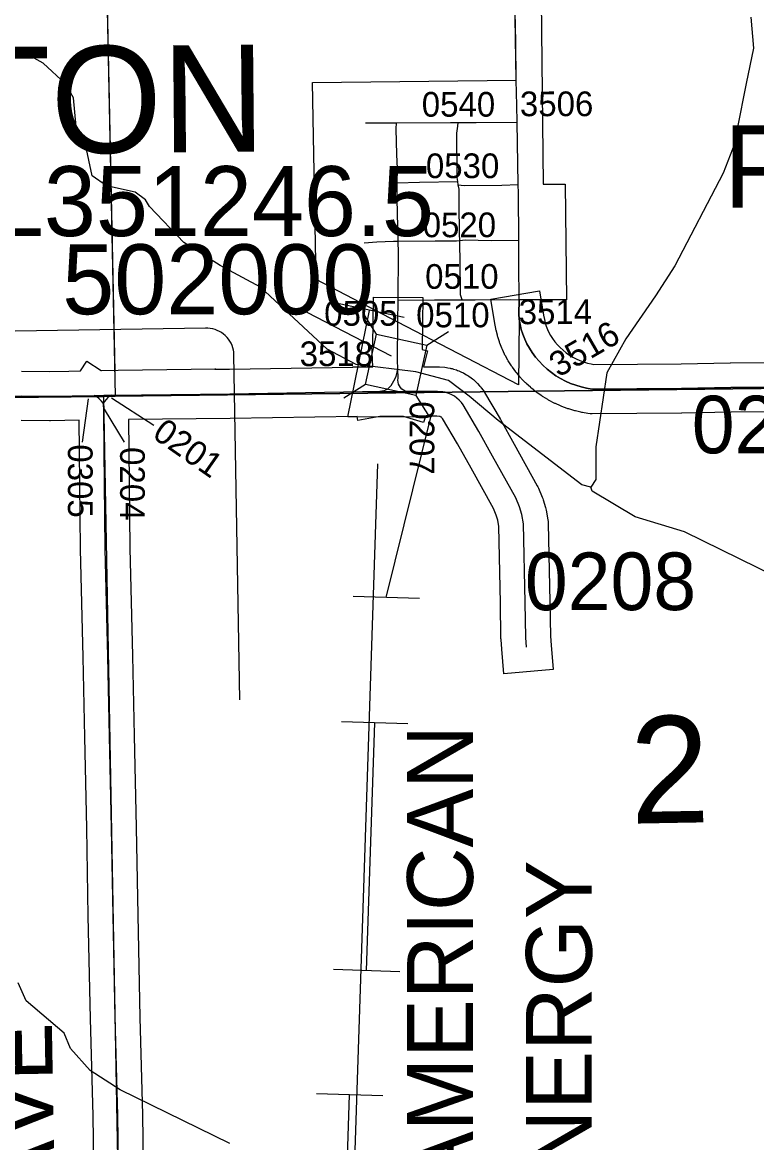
# Model space of a CAD drawing. Extents: x 23.6 to 68.7, y -63 to -29.
# Drawn here: x 36.588 to 37.481, y -46.611 to -45.249 of the extents above; entities that cross this region are included whole.
import ezdxf

# ---------------------------------------------------------------- set-up
doc = ezdxf.new("R2010")
doc.units = 0
for name, color, linetype in [('tdCoCityStreetMinor', 7, 'Continuous'), ('tdCoCorpBndry', 7, 'Continuous'), ('tdCoCorpPopTxt', 7, 'Continuous'), ('tdCoCorpTxt', 7, 'Continuous'), ('tdCoDirctArrow', 7, 'Continuous'), ('tdCoHydroRiver', 7, 'Continuous'), ('tdCoPipe', 7, 'Continuous'), ('tdCoPipeTxt', 7, 'Continuous'), ('tdCoSecRdNmbr', 7, 'Continuous'), ('tdCoSecRdTxt', 7, 'Continuous'), ('tdCoSecRteBand', 7, 'Continuous'), ('tdCoSecRteCL', 7, 'Continuous'), ('tdCoSectLine', 7, 'Continuous'), ('tdCoSectLinePart', 7, 'Continuous'), ('tdCoSectNmbr', 7, 'Continuous'), ('tdCoStrucSec', 7, 'Continuous'), ('tdCoStrucSecCoName', 7, 'Continuous'), ('tdCoStrucSecFHWANum', 7, 'Continuous'), ('tdCoSurfAsphalt', 7, 'Continuous'), ('tdCoSurfAsphaltUnbanded', 7, 'Continuous'), ('tdCoSurfConcUnbanded', 7, 'Continuous'), ('tdCoSurfGravel', 7, 'Continuous'), ('tdCoTwpBndryShd', 7, 'Continuous')]:
    doc.layers.add(name, color=color, linetype=linetype)

msp = doc.modelspace()

# ---------------------------------------------------------------- linework, layer by layer
at = {"layer": 'tdCoCityStreetMinor'}
for p, q in [((37.0054, -45.3713), (37.0429, -45.3713)), ((37.1181, -45.4467), (37.1175, -45.4426))]:
    msp.add_line(p, q, dxfattribs=at)
for points in [[(37.0439, -45.4442), (37.044, -45.4269), (37.0435, -45.41), (37.0424, -45.3787), (37.0429, -45.3713)], [(37.0429, -45.3713), (37.1088, -45.3711), (37.1181, -45.3711)], [(37.1175, -45.4426), (37.1168, -45.4379), (37.1163, -45.384), (37.1175, -45.3755), (37.1181, -45.3711)], [(37.1181, -45.3711), (37.14, -45.3709), (37.1895, -45.3707)], [(37.0451, -45.5153), (37.0437, -45.4637), (37.0439, -45.4442)], [(37.0439, -45.4442), (37.0711, -45.4435), (37.1175, -45.4426)], [(37.1181, -45.4467), (37.1254, -45.4476), (37.1711, -45.4473), (37.1909, -45.4463)], [(37.1198, -45.5143), (37.1196, -45.5067), (37.1193, -45.4698), (37.119, -45.4522), (37.1181, -45.4467)], [(37.0037, -45.5175), (37.0192, -45.516), (37.0392, -45.5154), (37.0451, -45.5153)], [(37.0449, -45.5869), (37.0455, -45.5293), (37.0451, -45.5153)], [(37.0451, -45.5153), (37.0899, -45.5149), (37.1159, -45.5147), (37.1198, -45.5143)], [(37.1198, -45.5143), (37.1264, -45.5136), (37.1579, -45.5144), (37.1915, -45.5139)], [(37.1226, -45.5866), (37.1209, -45.5806), (37.1208, -45.5737), (37.1198, -45.5143)]]:
    msp.add_lwpolyline(points, dxfattribs=at)
at = {"layer": 'tdCoCorpBndry'}
msp.add_lwpolyline([(37.2974, -45.1915), (37.2983, -45.2218), (37.2187, -45.2226), (37.2214, -45.446), (37.2481, -45.4462), (37.2495, -45.5866), (37.1921, -45.5865), (37.1916, -45.6041), (37.1922, -45.6103), (37.1912, -45.6899), (37.0447, -45.6136), (36.9452, -45.5618), (36.9409, -45.3224), (37.1886, -45.3197), (37.1866, -45.1925)], close=True, dxfattribs=at)
at = {"layer": 'tdCoDirctArrow'}
msp.add_lwpolyline([(36.8525, -46.0728), (36.8454, -45.6535), (36.8451, -45.6499), (36.8447, -45.6477), (36.844, -45.6448), (36.8431, -45.6421), (36.8419, -45.6394), (36.8404, -45.6369), (36.8388, -45.6345), (36.837, -45.6322), (36.8349, -45.6301), (36.8327, -45.6282), (36.8303, -45.6265), (36.8278, -45.625), (36.8252, -45.6238), (36.8224, -45.6228), (36.8196, -45.622), (36.8167, -45.6215), (36.8138, -45.6212), (36.8109, -45.6212), (36.4251, -45.6272)], dxfattribs=at)
at = {"layer": 'tdCoHydroRiver'}
for points in [[(37.4735, -45.243), (37.4769, -45.2808), (37.4678, -45.3235), (37.4572, -45.3789), (37.4542, -45.3963), (37.4402, -45.4327), (37.3812, -45.5452), (37.3578, -45.5817), (37.3219, -45.6341), (37.2985, -45.6753), (37.2851, -45.7654), (37.2854, -45.8049), (37.2791, -45.8144)], [(37.2791, -45.8144), (37.2681, -45.8113), (37.1664, -45.7332), (37.1315, -45.7035), (37.106, -45.6848), (37.0665, -45.674), (36.9938, -45.6652), (36.9589, -45.6465), (36.8778, -45.5714), (36.8287, -45.5449), (36.7843, -45.5169), (36.7429, -45.473), (36.7381, -45.4652), (36.7254, -45.4558), (36.6906, -45.4482), (36.6731, -45.4357), (36.6649, -45.3979), (36.6537, -45.3759), (36.6503, -45.3412), (36.6407, -45.3239), (36.6136, -45.2988), (36.5772, -45.2786)], [(38.2852, -46.2735), (38.2443, -46.2896), (38.2111, -46.2883), (37.8069, -46.0785), (37.7199, -46.0508), (37.6564, -46.0118), (37.6262, -45.9868), (37.5929, -45.9666), (37.3932, -45.8687), (37.3331, -45.8503), (37.2808, -45.8191), (37.2791, -45.8144)], [(36.8404, -46.6119), (36.7073, -46.5467), (36.6708, -46.5233), (36.6469, -46.4967), (36.6389, -46.4778), (36.5928, -46.4387), (36.5831, -46.4167)]]:
    msp.add_lwpolyline(points, dxfattribs=at)
at = {"layer": 'tdCoPipe'}
for p, q in [((37.0523, -45.6082), (36.9735, -45.5916)), ((37.0708, -45.9497), (36.9903, -45.9471)), ((37.0568, -46.102), (36.9761, -46.0994)), ((37.0469, -46.4032), (36.9664, -46.4005)), ((37.0262, -46.5542), (36.9456, -46.5516))]:
    msp.add_line(p, q, dxfattribs=at)
for points in [[(37.0305, -45.9484), (37.0848, -45.7291), (36.9839, -45.7287), (37.0102, -45.5995)], [(36.6897, -48.1748), (36.9749, -47.1608), (37.0201, -45.7858)], [(37.0066, -46.4018), (37.0165, -46.1007)], [(36.976, -46.854), (36.9859, -46.5529)]]:
    msp.add_lwpolyline(points, dxfattribs=at)
at = {"layer": 'tdCoSecRdNmbr'}
for p, q in [((36.7479, -45.7394), (36.6966, -45.7061)), ((36.7125, -45.7598), (36.6879, -45.7196))]:
    msp.add_line(p, q, dxfattribs=at)
msp.add_lwpolyline([(36.6612, -45.7594), (36.6688, -45.707), (36.6688, -45.707)], dxfattribs=at)
at = {"layer": 'tdCoSecRteBand'}
for points in [[(36.5871, -45.6732), (36.6216, -45.6737), (36.6449, -45.6732), (36.6449, -45.6731), (36.659, -45.6729), (36.6666, -45.6611), (36.684, -45.6725), (36.6843, -45.6725), (36.7048, -45.6721), (36.7048, -45.6722), (36.823, -45.6705), (36.8223, -45.6709), (36.84, -45.6707), (36.99, -45.6684), (36.99, -45.6682), (37.0012, -45.6682), (37.0015, -45.6682), (37.0143, -45.6682), (37.0144, -45.6681), (37.0132, -45.6422), (37.0144, -45.6422), (37.0147, -45.6133), (37.015, -45.5833), (37.075, -45.5839), (37.0747, -45.6139), (37.0743, -45.6469), (37.0805, -45.6484), (37.0759, -45.6681), (37.0927, -45.668), (37.094, -45.668), (37.0953, -45.6681), (37.1017, -45.6686), (37.1036, -45.6687), (37.1055, -45.6691), (37.1082, -45.6697), (37.1091, -45.6699), (37.1107, -45.6702), (37.1122, -45.6707), (37.1158, -45.6718), (37.1173, -45.6723), (37.1187, -45.6729), (37.1221, -45.6744), (37.1236, -45.6751), (37.1249, -45.6758), (37.1282, -45.6777), (37.1296, -45.6785), (37.1308, -45.6794), (37.1339, -45.6816), (37.1352, -45.6825), (37.1364, -45.6835), (37.1392, -45.686), (37.1403, -45.6871), (37.1414, -45.6882), (37.1439, -45.691), (37.145, -45.6921), (37.1459, -45.6934), (37.1482, -45.6964), (37.1491, -45.6977), (37.1499, -45.6991), (37.1689, -45.7314), (37.1691, -45.7317), (37.1692, -45.732), (37.186, -45.7621), (37.186, -45.7621), (37.186, -45.7621), (37.2141, -45.8126), (37.2149, -45.814), (37.2155, -45.8155), (37.2202, -45.8266), (37.2209, -45.8282), (37.2213, -45.8298), (37.2241, -45.8389), (37.2246, -45.8406), (37.2249, -45.8424), (37.2269, -45.854), (37.2272, -45.8562), (37.2273, -45.8584), (37.2292, -45.9538), (37.2292, -45.9539), (37.2292, -45.9539), (37.23, -45.9954), (37.2309, -46.0062), (37.2334, -46.0361), (37.1736, -46.0411), (37.1711, -46.0112), (37.1701, -45.9994), (37.17, -45.9984), (37.17, -45.9974), (37.1693, -45.955), (37.1673, -45.8619), (37.166, -45.8542), (37.1643, -45.8484), (37.1609, -45.8404), (37.1336, -45.7913), (37.117, -45.7615), (37.099, -45.7308), (37.0986, -45.7303), (37.0982, -45.7299), (37.0977, -45.7294), (37.0972, -45.7291), (37.0966, -45.7288), (37.0961, -45.7285), (37.0954, -45.7283), (37.0952, -45.7282), (37.0919, -45.728), (37.0859, -45.7281), (37.0859, -45.7282), (37.0781, -45.7282), (37.0758, -45.7357), (37.0514, -45.7282), (37.05, -45.7282), (37.0401, -45.7282), (37.0259, -45.7282), (37.0228, -45.7282), (36.996, -45.7332), (36.9951, -45.7283), (36.8409, -45.7307), (36.8408, -45.7307), (36.8408, -45.7307), (36.7172, -45.7321), (36.7175, -45.7697), (36.719, -45.8886), (36.722, -46.0194), (36.7243, -46.1166), (36.7243, -46.1166), (36.7243, -46.1167), (36.7266, -46.2277), (36.7266, -46.2277), (36.7266, -46.2278), (36.7284, -46.3345), (36.7312, -46.4587), (36.7341, -46.5772), (36.7341, -46.5774), (36.7341, -46.5775), (36.7358, -46.6934)], [(37.6364, -45.7223), (37.4496, -45.723), (37.39, -45.7243), (37.3898, -45.7243), (37.3895, -45.7243), (37.2807, -45.725), (37.2782, -45.725), (37.2757, -45.7246), (37.269, -45.7235), (37.2681, -45.7234), (37.2671, -45.7231), (37.2606, -45.7216), (37.2597, -45.7214), (37.2587, -45.7211), (37.2523, -45.7192), (37.2514, -45.7189), (37.2504, -45.7186), (37.2441, -45.7163), (37.2432, -45.7159), (37.2424, -45.7155), (37.2362, -45.7128), (37.2353, -45.7124), (37.2345, -45.712), (37.2285, -45.7088), (37.2277, -45.7084), (37.2268, -45.7079), (37.2211, -45.7044), (37.2203, -45.7039), (37.2195, -45.7033), (37.214, -45.6995), (37.2132, -45.6989), (37.2124, -45.6983), (37.2072, -45.6941), (37.2064, -45.6935), (37.2057, -45.6928), (37.2007, -45.6883), (37.2, -45.6876), (37.1994, -45.6869), (37.1947, -45.6821), (37.194, -45.6814), (37.1934, -45.6807), (37.1891, -45.6755), (37.1885, -45.6748), (37.1879, -45.674), (37.1839, -45.6686), (37.1833, -45.6678), (37.1828, -45.667), (37.1794, -45.6618), (37.1789, -45.6609), (37.1784, -45.6601), (37.1753, -45.6546), (37.1748, -45.6537), (37.1744, -45.6528), (37.1717, -45.6471), (37.1713, -45.6462), (37.1709, -45.6453), (37.1687, -45.6394), (37.1683, -45.6385), (37.168, -45.6375), (37.1661, -45.6316), (37.1658, -45.6306), (37.1656, -45.6296), (37.1641, -45.6235), (37.1639, -45.6225), (37.1637, -45.6215), (37.1626, -45.6154), (37.1576, -45.5858), (37.2167, -45.5756), (37.2218, -45.6052), (37.2227, -45.6104), (37.2237, -45.6145), (37.2249, -45.6186), (37.2265, -45.6225), (37.2283, -45.6263), (37.2303, -45.6301), (37.2327, -45.6337), (37.2355, -45.6376), (37.2386, -45.6412), (37.242, -45.6447), (37.2455, -45.6479), (37.2492, -45.6509), (37.2532, -45.6537), (37.2573, -45.6562), (37.2615, -45.6584), (37.2659, -45.6603), (37.2704, -45.662), (37.275, -45.6634), (37.2796, -45.6644), (37.2828, -45.665), (37.3889, -45.6643), (37.4485, -45.663), (37.4488, -45.663), (37.4491, -45.663), (37.6361, -45.6624)], [(36.6758, -46.6943), (36.6742, -46.5786), (36.6712, -46.4602), (36.6712, -46.4601), (36.6712, -46.4601), (36.6684, -46.3358), (36.6684, -46.3357), (36.6684, -46.3356), (36.6666, -46.2288), (36.6643, -46.118), (36.662, -46.0209), (36.662, -46.0208), (36.662, -46.0208), (36.659, -45.8898), (36.659, -45.8896), (36.659, -45.8895), (36.6575, -45.7705), (36.6575, -45.7704), (36.6575, -45.7704), (36.6572, -45.733), (36.6223, -45.7337), (36.6218, -45.7337), (36.6213, -45.7337), (36.5866, -45.7332)]]:
    msp.add_lwpolyline(points, dxfattribs=at)
at = {"layer": 'tdCoSecRteCL'}
for points in [[(37.1921, -45.5865), (37.1917, -45.5437), (37.1915, -45.5139), (37.1911, -45.4568), (37.1909, -45.4463), (37.1895, -45.3707), (37.1895, -45.3707), (37.1891, -45.3504), (37.1886, -45.3197), (37.1886, -45.3193), (37.1879, -45.273), (37.1871, -45.2365)], [(37.0445, -45.6709), (37.0442, -45.6597), (37.0447, -45.6136), (37.0449, -45.5869), (37.0892, -45.5867), (37.1226, -45.5866), (37.1386, -45.5865), (37.1819, -45.5863), (37.1921, -45.5865)], [(37.6363, -45.6923), (37.4492, -45.693), (37.3893, -45.6943), (37.2805, -45.695), (37.2739, -45.6939), (37.2673, -45.6924), (37.2609, -45.6905), (37.2546, -45.6881), (37.2484, -45.6854), (37.2425, -45.6823), (37.2367, -45.6788), (37.2312, -45.6749), (37.226, -45.6707), (37.221, -45.6662), (37.2163, -45.6613), (37.212, -45.6562), (37.208, -45.6508), (37.2046, -45.6455), (37.2016, -45.64), (37.1989, -45.6344), (37.1966, -45.6285), (37.1947, -45.6226), (37.1933, -45.6165), (37.1922, -45.6103), (37.1916, -45.6041), (37.1921, -45.5865)], [(37.02, -45.6982), (37.028, -45.6967), (37.0319, -45.695), (37.0364, -45.6906), (37.0397, -45.6852), (37.0425, -45.6796), (37.0445, -45.6709)], [(37.0559, -45.6982), (37.0536, -45.6975), (37.0514, -45.6964), (37.0495, -45.695), (37.0478, -45.6933), (37.0465, -45.6912), (37.0455, -45.689), (37.0449, -45.6867), (37.0448, -45.6843), (37.045, -45.6819), (37.0445, -45.6709)], [(35.9321, -45.7108), (36.0562, -45.7096), (36.1564, -45.7081), (36.3191, -45.7069), (36.4397, -45.7046), (36.5867, -45.7032), (36.6217, -45.7037), (36.6754, -45.7027)], [(36.6754, -45.7027), (36.6871, -45.7025), (36.6971, -45.7023)], [(36.6867, -45.7127), (36.6843, -45.7098), (36.6815, -45.7071), (36.6786, -45.7047), (36.6754, -45.7027)], [(36.6971, -45.7023), (36.6944, -45.7037), (36.692, -45.7055), (36.6899, -45.7076), (36.6881, -45.71), (36.6867, -45.7127)], [(36.6971, -45.7023), (36.8404, -45.7007), (37.0015, -45.6982), (37.02, -45.6982)], [(37.02, -45.6982), (37.0401, -45.6982), (37.0559, -45.6982)], [(37.201, -46.0087), (37.2, -45.9969), (37.1993, -45.9545), (37.1973, -45.859), (37.1953, -45.8474), (37.1926, -45.8383), (37.1879, -45.8272), (37.1598, -45.7767), (37.143, -45.7466), (37.124, -45.7143), (37.1218, -45.7112), (37.1193, -45.7085), (37.1164, -45.706), (37.1134, -45.7038), (37.1101, -45.7019), (37.1067, -45.7004), (37.1031, -45.6992), (37.1021, -45.699), (37.0994, -45.6985), (37.093, -45.698), (37.0644, -45.6982), (37.0559, -45.6982)], [(36.7129, -47.1747), (36.7124, -47.1509), (36.7106, -47.0309), (36.7096, -46.9323), (36.7078, -46.8099), (36.7058, -46.6939), (36.7041, -46.578), (36.7012, -46.4594), (36.6984, -46.3351), (36.6966, -46.2283), (36.6943, -46.1173), (36.692, -46.0201), (36.689, -45.8891), (36.6875, -45.7701), (36.6871, -45.7211), (36.6867, -45.7127)]]:
    msp.add_lwpolyline(points, dxfattribs=at)
at = {"layer": 'tdCoSectLine'}
for points in [[(36.6803, -44.7056), (36.7012, -45.7036)], [(36.7012, -45.7036), (37.6909, -45.6918)], [(35.6948, -45.7141), (36.6871, -45.7039)], [(36.6871, -45.7039), (36.7012, -45.7036)], [(36.7052, -46.6743), (36.6871, -45.7039)]]:
    msp.add_lwpolyline(points, dxfattribs=at)
at = {"layer": 'tdCoSectLinePart'}
for points in [[(36.6803, -44.7056), (36.7006, -45.6736)], [(37.1489, -45.6982), (37.2118, -45.6975)]]:
    msp.add_lwpolyline(points, dxfattribs=at)
at = {"layer": 'tdCoStrucSec'}
for p, q in [((37.0188, -45.6283), (37.002, -45.6019)), ((37.0799, -45.6418), (37.1063, -45.625)), ((37.0052, -45.6894), (36.9788, -45.7062)), ((37.0663, -45.7029), (37.0831, -45.7293))]:
    msp.add_line(p, q, dxfattribs=at)
msp.add_lwpolyline([(37.0052, -45.6894), (37.0188, -45.6283), (37.0799, -45.6418), (37.0663, -45.7029)], close=True, dxfattribs=at)
at = {"layer": 'tdCoStrucSecFHWANum'}
msp.add_line((36.9342, -45.6017), (37.0365, -45.6545), dxfattribs=at)
at = {"layer": 'tdCoSurfAsphalt'}
msp.add_lwpolyline([(37.1922, -45.6103), (37.1933, -45.6165), (37.1947, -45.6226), (37.1966, -45.6285), (37.1989, -45.6344), (37.2016, -45.64), (37.2046, -45.6455), (37.208, -45.6508), (37.212, -45.6562), (37.2163, -45.6613), (37.221, -45.6662), (37.226, -45.6707), (37.2312, -45.6749), (37.2367, -45.6788), (37.2425, -45.6823), (37.2484, -45.6854), (37.2546, -45.6881), (37.2609, -45.6905), (37.2673, -45.6924), (37.2739, -45.6939), (37.2805, -45.695), (37.3893, -45.6943), (37.4492, -45.693), (37.6363, -45.6923)], dxfattribs=at)
at = {"layer": 'tdCoSurfAsphaltUnbanded'}
msp.add_line((37.0447, -45.6136), (37.0449, -45.5869), dxfattribs=at)
for points in [[(37.1886, -45.3193), (37.1879, -45.273), (37.1871, -45.2365), (37.1866, -45.1925)], [(37.1922, -45.6103), (37.1916, -45.6041), (37.1921, -45.5865)]]:
    msp.add_lwpolyline(points, dxfattribs=at)
at = {"layer": 'tdCoSurfConcUnbanded'}
msp.add_lwpolyline([(37.0449, -45.5869), (37.0892, -45.5867), (37.1226, -45.5866), (37.1386, -45.5865), (37.1819, -45.5863), (37.1921, -45.5865), (37.1917, -45.5437), (37.1915, -45.5139), (37.1911, -45.4568), (37.1909, -45.4463), (37.1895, -45.3707), (37.1895, -45.3707), (37.1891, -45.3504), (37.1886, -45.3197)], dxfattribs=at)
at = {"layer": 'tdCoSurfGravel'}
msp.add_line((37.02, -45.6982), (37.0401, -45.6982), dxfattribs=at)
for points in [[(37.02, -45.6982), (37.028, -45.6967), (37.0319, -45.695), (37.0364, -45.6906), (37.0397, -45.6852), (37.0425, -45.6796), (37.0445, -45.6709), (37.0442, -45.6597), (37.0447, -45.6136)], [(37.0559, -45.6982), (37.0536, -45.6975), (37.0514, -45.6964), (37.0495, -45.695), (37.0478, -45.6933), (37.0465, -45.6912), (37.0455, -45.689), (37.0449, -45.6867), (37.0448, -45.6843), (37.045, -45.6819), (37.0445, -45.6709)], [(36.5867, -45.7032), (36.6217, -45.7037), (36.6754, -45.7027), (36.6871, -45.7025)], [(36.6867, -45.7127), (36.6843, -45.7098), (36.6815, -45.7071), (36.6786, -45.7047), (36.6754, -45.7027)], [(36.6971, -45.7023), (36.6944, -45.7037), (36.692, -45.7055), (36.6899, -45.7076), (36.6881, -45.71), (36.6867, -45.7127)], [(36.6871, -45.7025), (36.6971, -45.7023), (36.8404, -45.7007), (37.0015, -45.6982), (37.02, -45.6982)], [(37.0401, -45.6982), (37.0559, -45.6982), (37.0644, -45.6982), (37.093, -45.698), (37.0994, -45.6985), (37.1021, -45.699)], [(37.201, -46.0087), (37.2, -45.9969), (37.1993, -45.9545), (37.1973, -45.859), (37.1953, -45.8474), (37.1926, -45.8383), (37.1879, -45.8272), (37.1598, -45.7767), (37.143, -45.7466), (37.124, -45.7143), (37.1218, -45.7112), (37.1193, -45.7085), (37.1164, -45.706), (37.1134, -45.7038), (37.1101, -45.7019), (37.1067, -45.7004), (37.1031, -45.6992), (37.1021, -45.699)], [(36.7058, -46.6939), (36.7041, -46.578), (36.7012, -46.4594), (36.6984, -46.3351), (36.6966, -46.2283), (36.6943, -46.1173), (36.692, -46.0201), (36.689, -45.8891), (36.6875, -45.7701), (36.6871, -45.7211), (36.6867, -45.7127)]]:
    msp.add_lwpolyline(points, dxfattribs=at)
at = {"layer": 'tdCoTwpBndryShd'}
msp.add_lwpolyline([(44.659, -45.6063), (43.6569, -45.6219), (42.6564, -45.6349), (41.6548, -45.649), (40.661, -45.6604), (39.6539, -45.6718), (38.6948, -45.6802), (37.6909, -45.6918), (36.7012, -45.7036), (36.6871, -45.7039), (35.6948, -45.7141), (35.6828, -45.7143), (34.6942, -45.7256), (34.6845, -45.726), (33.6895, -45.7373), (33.6806, -45.7374), (32.7232, -45.7449)], dxfattribs=at)

# ---------------------------------------------------------------- texts
at = {"layer": 'tdCoCorpPopTxt'}
msp.add_text('POP.', height=0.1, dxfattribs=at).set_placement((37.4405, -45.4747))
at = {"layer": 'tdCoCorpTxt'}
msp.add_text('LEIGHTON', height=0.13, rotation=0.5307, dxfattribs=at).set_placement((35.9954, -45.4145))
at = {"layer": 'tdCoPipeTxt'}
for s, p in [('MIDAMERICAN', (37.1359, -46.8644)), ('ENERGY', (37.2804, -46.7196))]:
    msp.add_text(s, height=0.08, rotation=90, dxfattribs=at).set_placement(p)
at = {"layer": 'tdCoSecRdNmbr'}
for s, height, rotation, p in [('0540', 0.03, 0.0292, (37.0737, -45.364)), ('3506', 0.03, 0.0292, (37.193, -45.3634)), ('0530', 0.03, 0.0292, (37.0787, -45.4387)), ('0520', 0.03, 0.0292, (37.0748, -45.5105)), ('0510', 0.03, 0.0292, (37.0778, -45.5732)), ('0505', 0.03, 0.0292, (36.9551, -45.6181)), ('0510', 0.03, 0.0292, (37.0669, -45.62)), ('3514', 0.03, 0.0292, (37.1915, -45.6162)), ('3516', 0.03, 30.0285, (37.2399, -45.6814)), ('3518', 0.03, 0.0292, (36.9253, -45.6672)), ('0209', 0.07, 0.0294, (37.4019, -45.7732)), ('0207', 0.03, 270.0269, (37.0589, -45.7099)), ('0201', 0.03, 325.0283, (36.7447, -45.7533)), ('0305', 0.03, 270.0266, (36.6436, -45.7622)), ('0204', 0.03, 270.0266, (36.707, -45.7656)), ('0208', 0.07, 0.0292, (37.199, -45.9638))]:
    msp.add_text(s, height=height, rotation=rotation, dxfattribs=at).set_placement(p)
at = {"layer": 'tdCoSecRdTxt'}
msp.add_text('DEAN AVE', height=0.08, rotation=91, dxfattribs=at).set_placement((36.6335, -47.0054))
at = {"layer": 'tdCoSectNmbr'}
msp.add_text('2', height=0.13, rotation=1.0291, dxfattribs=at).set_placement((37.3279, -46.2233))
at = {"layer": 'tdCoStrucSecCoName'}
msp.add_text('BL351246.5', height=0.085, dxfattribs=at).set_placement((36.4754, -45.5091))
at = {"layer": 'tdCoStrucSecFHWANum'}
msp.add_text('502000', height=0.085, dxfattribs=at).set_placement((36.6367, -45.6041))

doc.saveas('drawing.dxf')
